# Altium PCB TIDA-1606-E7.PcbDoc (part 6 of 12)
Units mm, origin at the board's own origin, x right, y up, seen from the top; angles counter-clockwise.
Board outline 270 x 345 mm, 4 copper layers (Top Layer, Signal Layer 1, Signal Layer 2, Bottom Layer), stack 2.326 mm thick; 1282 components, 576 nets, 3628 pads, 4132 vias.
Unrouted connection lines stored in the file: 1719.
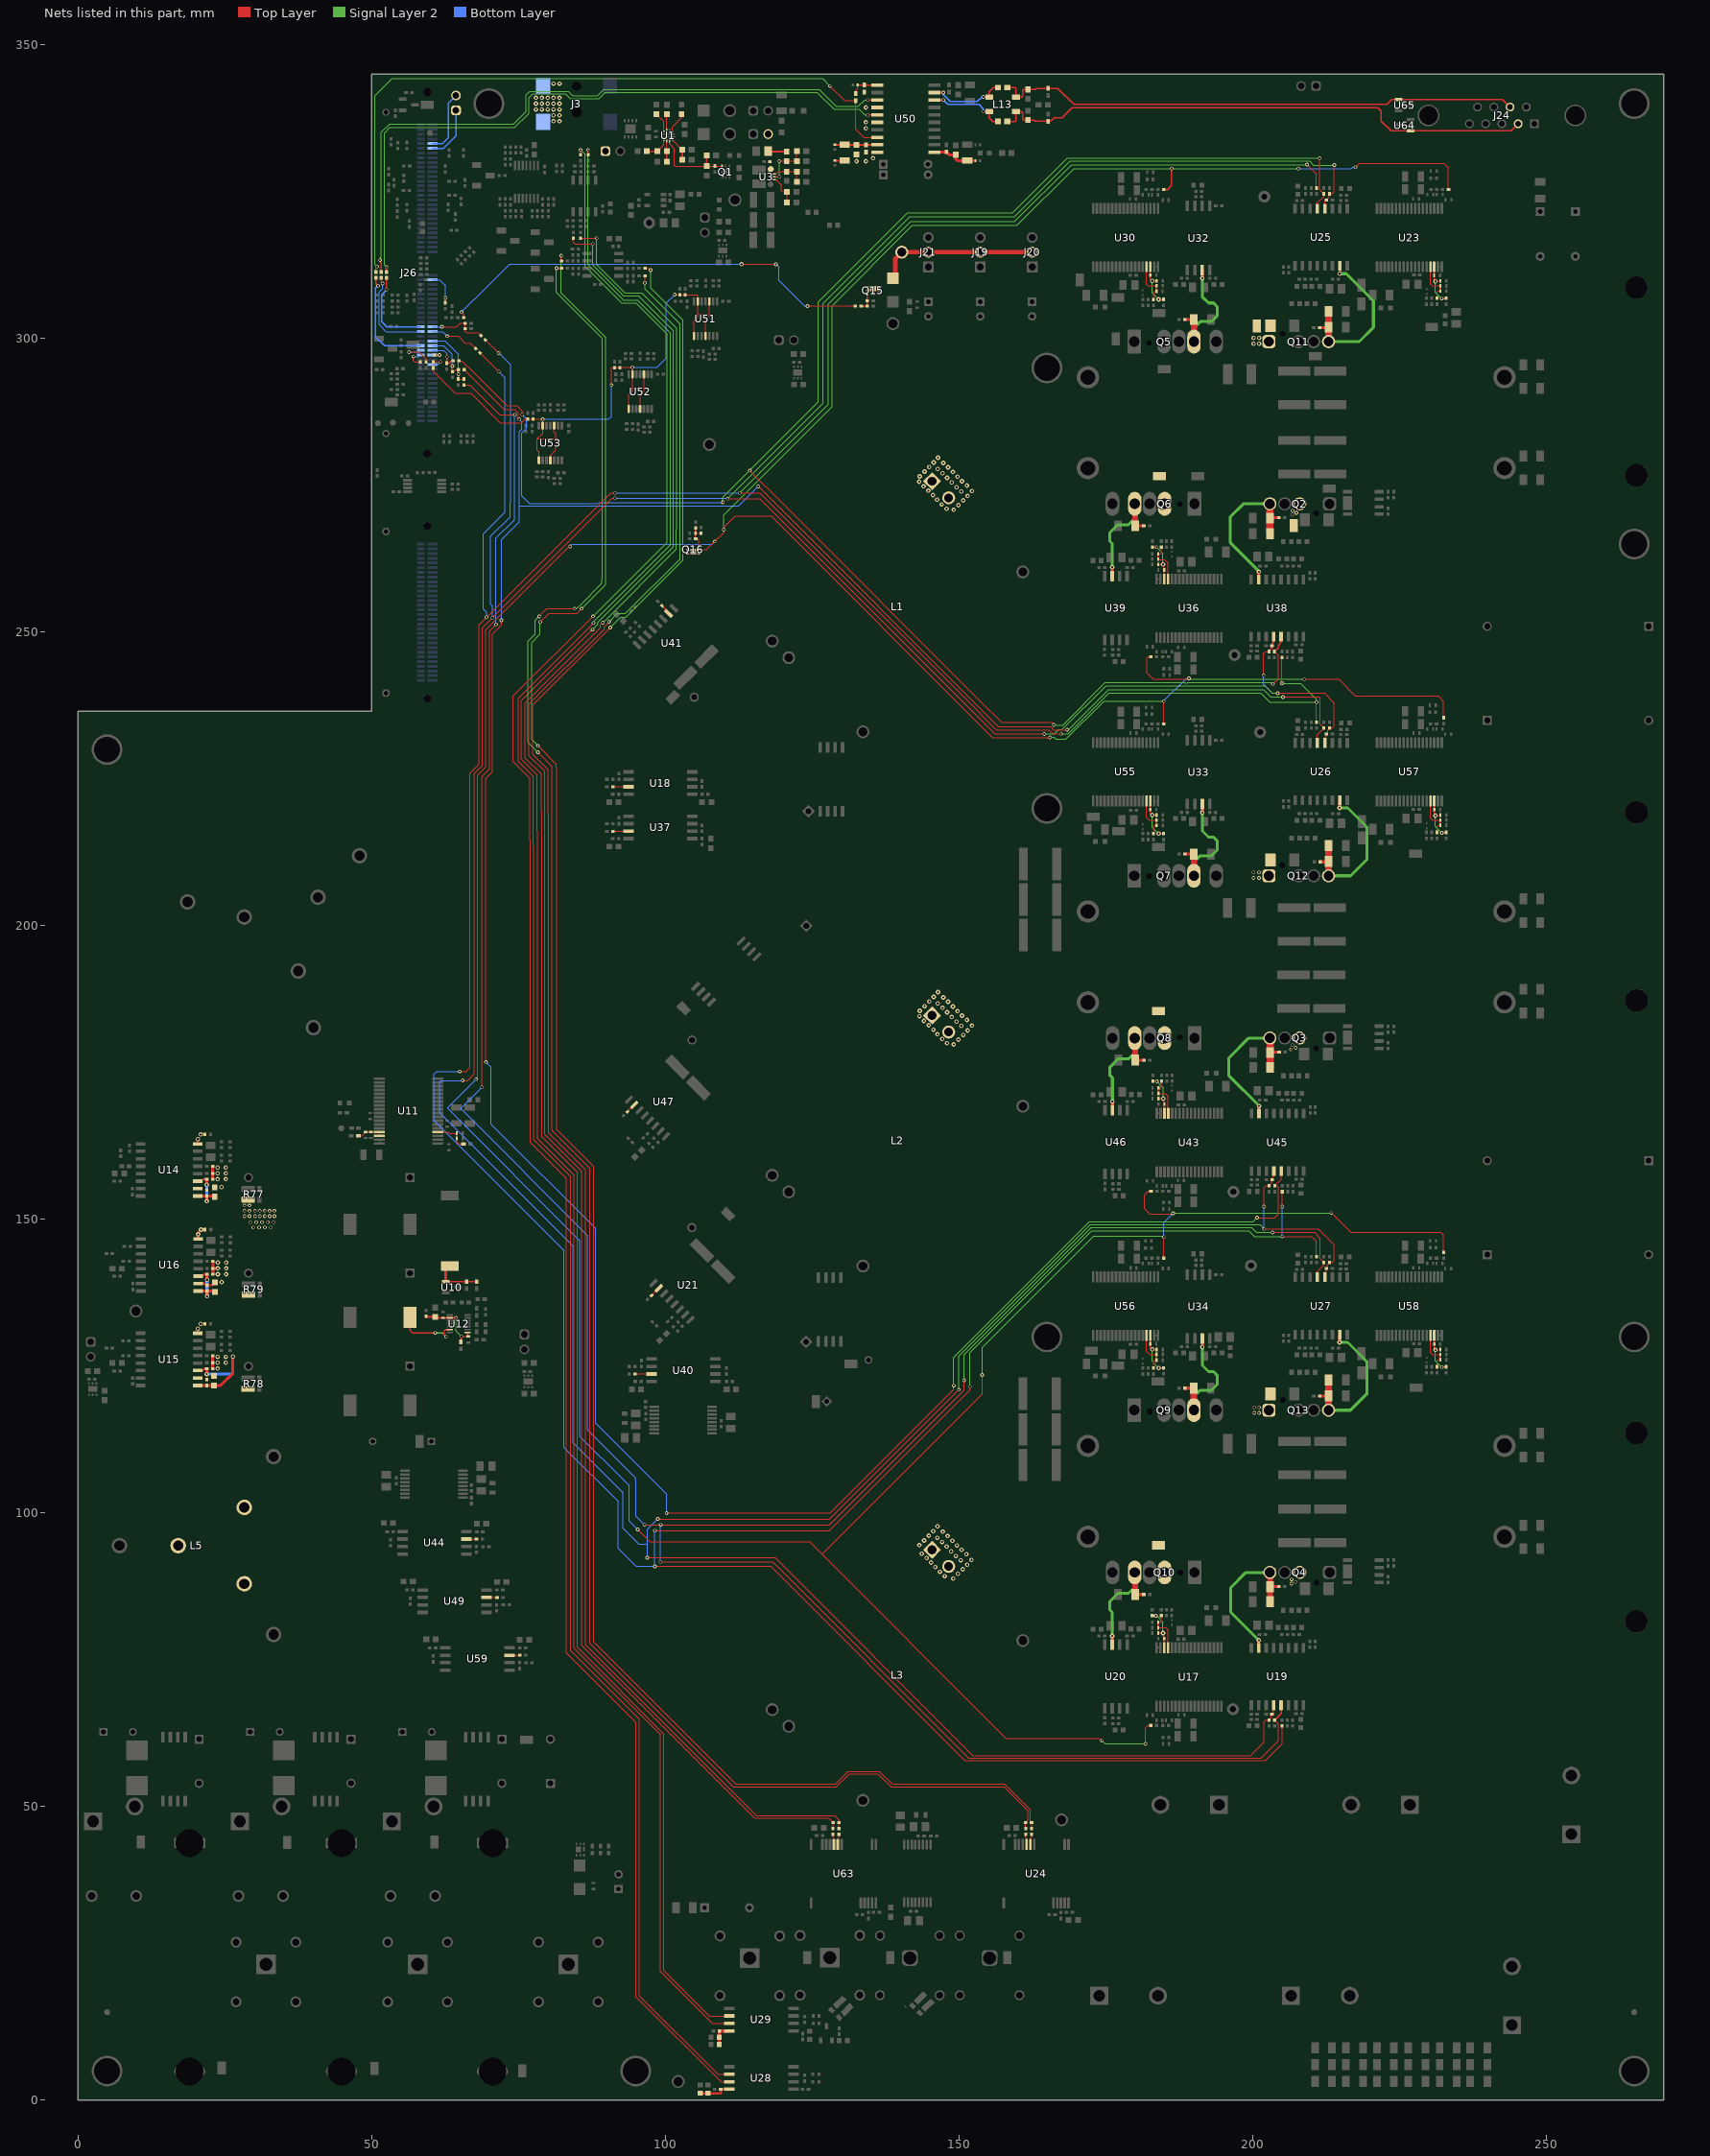
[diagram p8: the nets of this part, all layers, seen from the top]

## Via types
v1: diameter 0.762, hole 0.356, Top Layer to Bottom Layer, tented both sides, 2905 vias
v2: diameter 0.61, hole 0.356, Top Layer to Bottom Layer, tented both sides, 1212 vias
v3: diameter 0.864, hole 0.406, Top Layer to Bottom Layer, tented both sides, 15 vias

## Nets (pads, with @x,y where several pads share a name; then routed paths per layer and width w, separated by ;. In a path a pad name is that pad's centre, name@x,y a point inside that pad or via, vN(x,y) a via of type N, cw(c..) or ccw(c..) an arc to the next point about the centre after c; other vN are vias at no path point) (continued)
AEF_SENS3: C81.1 U12.6 | length 11.1
  Top Layer w0.254: C81.1@56.556,133.295 56.556,131.107 56.981,130.682 v2(60.834,130.682) ; v2(62.712,130) 62.335,130.377 62.335,130.964 62.609,131.238 U12.6@63.365,131.238
  Signal Layer 2 w0.254: v2(60.834,130.682) 62.03,130.682 v2(62.712,130)
AEF_TVS_PT: C7.1 C84.1 R64.2 U10.1 | length 8.2
  Top Layer w0.305: U10.1@62.649,139.401 C7.1@67.902,139.401
  Top Layer w0.508: U10.1@62.649,139.401 62.649,141.348 C84.1@63.347,142.046
AEF_VDD: C92.1 C96.1 C97.1 R71.1 R74.2 U12.2 U12.8 | length 11.2
  Top Layer w0.203: R74.2@65.246,129.167 65.293,129.213 65.293,130.069 v2(65.311,130.088) C96.1@66.389,130.088
  Top Layer w0.254: R71.1@59.333,133.393 C97.1@60.862,133.393 ; C97.1@61.1,133.238 C92.1@62.183,133.238 U12.2@63.365,133.238 v2(64.412,133.238) ; U12.8@66.365,130.738 66.389,130.714 66.389,130.088 66.413,130.064 C96.1@66.5,130.064
  Signal Layer 2 w0.203: v2(64.412,133.238) 64.412,130.987 v2(65.311,130.088)
ALERT_L1: R308.2 U41.4 | length 1.8
  Top Layer w0.229: R308.2@99.466,254.5 100.602,253.364 U41.4@100.602,253.185
ALERT_L2: R340.2 U47.4 | length 1.6
  Top Layer w0.203: R340.2@93.6,168.356 93.6,168.365 U47.4@94.743,169.508
ALERT_L3: R178.2 U21.4 | length 1.7
  Top Layer w0.203: R178.2@97.693,137.054 98.904,138.266 U21.4@98.93,138.266
AMC13x_VDD_LO: C220.1 C221.1 L7.1 U28.8 | length 5.8
  Top Layer w0.381: L7.1@106,1.2 C221.1@107.3,1.2 107.3,1.187 109.537,1.187 109.537,1.806 C220.1@109.456,1.887 U28.8@110.95,1.887
AMC13x_VDD_MID: C269.1 C271.1 L8.2 U29.8 | length 4
  Top Layer w0.5: L8.2@109.237,9.5 C269.1@109.237,10.731 C271.1@109.237,11.8 110.93,11.8 U29.8@110.95,11.82
AMC033_OUT1: R171.1 U44.7 | length 1.7
  Top Layer w0.203: U44.7@66.187,95.56 R171.1@67.89,95.56
AMC033_OUT2: R222.1 U49.7 | length 1.8
  Top Layer w0.203: U49.7@69.613,85.626 R222.1@71.401,85.626
AMC033_OUT3: R251.1 U59.7 | length 1.8
  Top Layer w0.203: U59.7@73.497,75.786 R251.1@75.26,75.786
AMC033_SN_O1: R63.1 U18.7 | length 2.6
  Top Layer w0.203: R63.1@91.1,223.669 U18.7@93.75,223.669
AMC033_SN_O2: R68.1 U37.7 | length 2.7
  Top Layer w0.203: R68.1@91.1,216.104 U37.7@93.75,216.104
AMC033_SN_O3: R73.1 U40.7 | length 2.8
  Top Layer w0.203: R73.1@94.88,123.682 U40.7@97.693,123.682
AMC1302_OUTN_A: R274.1 U29.6 | length 339.8
  Top Layer w0.203: R274.1@85.614,317.089 v2(88.363,317.089) ; v2(89.408,251.603) 89.034,251.228 89.034,250.754 76.2,237.92 76.2,228.52 78.914,225.806 78.914,219.456 78.914,164.185 85.06,158.04 85.06,77.14 99.815,62.385 99.815,22.061 107.516,14.36 U29.6@110.95,14.36
  Signal Layer 2 w0.203: v2(88.363,317.089) 88.363,312.552 93.179,307.737 96.008,307.737 101.929,301.815 101.929,267.462 101.929,264.124 v2(89.408,251.603)
AMC1302_OUTN_B: R241.2 U28.6 | length 362.4
  Top Layer w0.203: R241.2@86.889,331.286 v2(86.889,332.099) v2@86.889,332.118 ; v2(87.82,251.568) 75,238.748 75,227.951 77.552,225.399 77.552,213.627 77.565,213.614 77.565,163.628 83.86,157.333 83.86,76.64 95.562,64.938 95.562,17.852 108.987,4.427 U28.6@110.95,4.427
  Signal Layer 2 w0.203: v2(86.889,332.099) 86.889,312.573 92.884,306.578 95.297,306.578 100.845,301.03 100.845,264.82 87.82,251.795 v2(87.82,251.568)
AMC1302_OUTP_A: R272.1 U29.7 | length 341.5
  Top Layer w0.203: R272.1@84.347,317.089 84.347,316.453 84.697,316.103 v2(87.702,316.103) v2@87.89,316.103 ; v2(87.63,250.444) 75.538,238.352 75.538,228.375 78.251,225.661 78.251,216.154 78.251,163.819 84.45,157.62 84.45,77.031 99.234,62.248 99.234,21.925 108.069,13.09 U29.7@110.95,13.09
  Signal Layer 2 w0.203: v2(87.63,250.444) 88.6,251.414 88.6,251.75 101.397,264.547 101.397,301.306 95.419,307.283 92.915,307.283 87.702,312.496 v2(87.702,316.103)
AMC1302_OUTP_B: R239.2 U28.7 | length 364.1
  Top Layer w0.203: R239.2@85.625,331.286 v2(85.625,332.099) ; v2(87.738,252.692) 74.168,239.122 74.168,227.94 77,225.108 77,214.63 77,163.172 83.148,157.024 83.148,76.252 94.998,64.402 94.998,17.709 109.55,3.157 U28.7@110.95,3.157
  Signal Layer 2 w0.203: v2(85.625,332.099) 86.36,331.363 86.36,312.302 92.592,306.07 95.019,306.07 100.315,300.774 100.315,265.269 v2(87.738,252.692)
AMC_DC_OUT1: C105.2 C106.1 C108.1 U14.1 U14.3 | length 9.2
  Top Layer w0.305: U14.3@21.106,156.52 21.442,156.856 C108.1@21.965,156.856
  Top Layer w0.35: U14.3@20.441,156.52 U14.3@21.106,156.52
  Top Layer w0.5: U14.1@20.441,153.98 C106.1@21.965,153.98 ; v1(21.965,155.909) C108.1@21.965,156.856 ; v1(21.97,153.109) 21.965,153.114 C106.1@21.965,153.98 ; C105.2@23.312,153.856 23.188,153.98 C106.1@21.965,153.98
  Bottom Layer w0.5: v1(21.965,155.909) 21.965,153.114 v1(21.97,153.109)
AMC_DC_OUT2: C114.2 C115.1 C117.1 U15.1 U15.3 | length 19.7
  Top Layer w0.305: U15.3@20.441,124.262 21.261,124.262 21.597,124.598 C117.1@21.965,124.598
  Top Layer w0.5: U15.1@20.441,121.722 C115.1@21.965,121.722 C114.2@23.188,121.722 24.319,121.722 26.409,123.812 v1(26.409,126.671) ; v1(21.965,123.651) C117.1@21.965,124.598
  Bottom Layer w0.5: v1(21.965,123.651) 26.248,123.651 26.409,123.812 v1(26.409,126.671)
AMC_DC_OUT3: C123.2 C124.1 C126.1 U16.1 U16.3 | length 9.2
  Top Layer w0.305: U16.3@20.483,140.335 21.184,140.335 21.52,140.671 C126.1@22.007,140.671
  Top Layer w0.5: U16.1@20.483,137.795 C124.1@22.007,137.795 ; v1(22.007,139.724) C126.1@22.007,140.671 ; v1(22.012,136.924) 22.007,136.929 C124.1@22.007,137.795 ; C123.2@23.354,137.671 23.23,137.795 C124.1@22.007,137.795
  Bottom Layer w0.5: v1(22.007,139.724) 22.007,136.924 v1(22.012,136.924)
AMC_HGND_L1: C105.1 C106.2 C108.2 C109.2 C111.2 FB3.2 U14.2 U14.8 | length 3.7
  Top Layer w0.254: U14.8@20.441,162.87 20.461,162.89 v1(20.461,163.658) ; v1(20.941,164.456) FB3.2@21.62,164.456
  Top Layer w0.5: C108.2@22.965,156.856 C109.2@22.965,157.856 C111.2@22.965,159.06
  other v1: 24.462,155.49 23.812,156.856 25.212,156.856 23.812,157.856 25.212,157.856 23.812,158.856 25.212,158.856
AMC_HGND_L2: C114.1 C115.2 C117.2 C118.2 C120.2 FB6.2 U15.2 U15.8 | length 2.2
  Top Layer w0.5: C117.2@22.965,124.598 C118.2@22.965,125.598 C120.2@22.965,126.802
  other v1: 23.812,124.598 23.812,125.598 25.212,125.598 23.812,126.598 25.212,126.598 20.461,131.4 20.941,132.198
AMC_HGND_L3: C123.1 C124.2 C126.2 C127.2 C129.2 FB9.2 U16.2 U16.8 | length 8.7
  Top Layer w0.35: U16.2@20.483,139.065 21.597,139.065 21.867,138.795 C124.2@22.007,138.795 22.878,138.795 C123.1@23.354,139.271
  Top Layer w0.5: U16.8@20.483,146.685 20.483,147.771 v1(20.983,148.271) FB9.2@21.662,148.271 ; C126.2@23.007,140.671 C127.2@23.007,141.671 ; C129.2@23.007,142.875 C127.2@23.007,141.671 ; v1(23.854,141.671) C127.2@23.007,141.671
  other v1: 24.504,139.305 23.854,140.671 25.254,140.671 25.254,141.671 23.854,142.671 25.254,142.671 20.503,147.473
AUX_IN_PWR: J1.1 J3.1 J3.1A
  other v1: 81.002,336.997 82.002,336.997 81.002,338 82.002,338 78.002,339 79.002,339 80.002,339 81.002,339 82.002,339 78.002,340.003 79.002,340.003 80.002,340.003 81.002,340.003 82.002,340.003 78.002,341 79.002,341 80.002,341 81.002,341 82.002,341 81.002,343.408 82.002,343.408
BUFF_EN: C102.1 C389.1 C470.1 R375.2 R381.2 R413.2 R466.1 U51.1 U51.4 U51.10 U51.13 U52.1 U52.4 U52.10 U52.13 U53.1 U53.4 U53.10 U53.13 | length 116.7
  Top Layer w0.203: R466.1@60.502,295 60.502,294.423 64.226,290.7 66.91,290.7 71.961,285.648 75.525,285.648 76.177,286.3 R413.2@76.602,286.3 C470.1@77.502,286.3 79.126,286.3 v2(79.162,286.265) U53.13@79.162,285.173 79.162,283.835 78.232,282.906 ; U53.1@78.512,279.273 78.512,280.72 78.232,281 78.232,282.906 ; U53.4@80.462,279.273 80.462,280.104 81.393,281.035 81.393,283 ; U53.10@81.112,285.173 81.112,284.089 81.393,283.808 81.393,283 ; v2(90.857,292.07) 90.857,295.039 90.932,295.114 v2(94.431,295.114) 94.452,295.092 U52.13@94.452,293.913 94.452,291.126 93.802,290.476 U52.1@93.802,288.013 ; R381.2@91.406,295.053 R381.2@91.427,295.032 ; 94.452,291.563 96.402,291.563 ; U52.4@95.752,288.013 95.752,290.438 96.402,291.088 U52.10@96.402,293.913 ; v2(101.637,307.471) R375.2@102.546,307.471 C102.1@103.446,307.471 103.46,307.457 105.396,307.457 105.593,307.26 U51.13@105.593,306.331 105.593,304.202 ; U51.1@104.943,300.431 104.943,303.056 105.593,303.706 105.593,304.202 ; U51.4@106.893,300.431 106.893,303.305 107.543,303.955 107.543,304.191 ; U51.10@107.543,306.331 107.543,304.191 ; 78.232,282.906 81.299,282.906 81.393,283 ; 105.593,304.202 105.604,304.191 107.543,304.191
  Bottom Layer w0.203: v2(79.162,286.265) 90.415,286.265 90.857,286.707 v2(90.857,292.07) ; v2(94.431,295.114) 98.65,295.114 100.214,296.678 100.214,306.048 v2(101.637,307.471)
BUFF_EN_IO: J26.26 R466.2 | length 2.9
  Top Layer w0.203: R466.2@60.502,296 v2(61.802,296)
  Bottom Layer w0.203: J26.26@60.402,295.585 61.388,295.585 v2(61.802,296)
CAN_EN: R383.1 R460.2 U50.8 | length 124
  Top Layer w0.203: R460.2@50.762,311.339 50.762,312.045 v2(50.987,312.27) ; v2(128.065,342.997) 130.541,340.521 R383.1@132.438,340.521 132.438,335.635 133.81,334.264 U50.8@136.144,334.264
  Signal Layer 2 w0.203: v2(50.987,312.27) 50.627,312.63 50.627,341.329 53.573,344.275 126.787,344.275 v2(128.065,342.997)
CAN_GND1: C370.2 C371.2 C372.2 C373.2 FB20.2 U50.4 U50.6 U50.10 | length 1.7
  Top Layer w0.305: FB20.2@128.88,330.303 C370.2@130.556,330.303
  other v1: 132.594,330.196 134.2,330.196 135.4,330.708 134.2,335.797 134.2,336.829 134.2,339.344
CAN_GND2: C380.2 C381.2 C382.2 FB19.1 U50.11 | length 8.1
  Top Layer w0.305: C382.2@151.494,330.271 FB19.1@152.841,330.271
  Top Layer w0.508: U50.11@145.844,331.724 147.836,331.724 C380.2@147.907,331.795 148.411,331.29 C381.2@149.474,331.29 149.474,330.54 149.743,330.271 C382.2@151.494,330.271
CAN_RX: R452.2 U50.5 | length 114.5
  Top Layer w0.229: R452.2@52.562,311.339 v2(52.562,312.164)
  Top Layer w0.305: v2(134.499,338.074) U50.5@136.144,338.074
  Signal Layer 2 w0.203: v2(52.562,312.164) 52.215,312.511 52.215,334.991 53.149,335.925 74.365,335.925 76.805,338.365 76.805,341.059 77.438,341.692 83.054,341.692 83.878,340.868 88.746,340.868 89.832,341.954 125.878,341.954 128.742,339.09 133.011,339.09 134.027,338.074 v2(134.499,338.074)
CAN_TX: R458.2 U50.3 | length 115.3
  Top Layer w0.229: v2(51.48,313.375) 51.48,313.032 51.662,312.85 R458.2@51.662,311.339
  Top Layer w0.305: v2(134.499,340.614) U50.3@136.144,340.614
  Signal Layer 2 w0.203: v2(51.48,313.375) 51.48,313.772 51.652,313.944 51.652,335.125 53.095,336.568 74.232,336.568 76.344,338.68 76.344,341.508 76.948,342.111 83.524,342.111 84.26,341.376 88.523,341.376 89.559,342.412 126.245,342.412 129.124,339.533 132.899,339.533 133.979,340.614 v2(134.499,340.614)
CAN_VDD: C370.1 C371.1 C372.1 FB16.2 U50.9 | length 7.3
  Top Layer w0.305: FB16.2@128.88,332.994 U50.9@136.144,332.994
CAN_VIO: C373.1 FB17.2 R383.2 U50.1 | length 4.9
  Top Layer w0.203: R383.2@132.438,341.721 132.438,342.202 132.789,342.552 FB17.2@132.789,343.154
  Top Layer w0.305: FB17.2@132.789,343.154 C373.1@133.949,343.154 U50.1@136.144,343.154
CANEN_IO: J26.33 R460.1 | length 18.7
  Top Layer w0.229: R460.1@50.762,310.339 50.762,309.358 v2(51.118,309.003)
  Bottom Layer w0.229: v2(51.118,309.003) 50.722,308.606 50.722,300.27 52.207,298.785 J26.33@58.402,298.785
CANH: L13.1 R384.2 U50.19 | length 13.2
  Top Layer w0.229: U50.19@145.844,341.884 v2(147.362,341.884) ; v2(154.178,341.138) L13.1@155.205,341.138 155.205,342.013 155.93,342.738 R384.2@156.68,342.738
  Bottom Layer w0.229: v2(147.362,341.884) 147.362,341.567 148.569,340.36 153.138,340.36 153.916,341.138 v2(154.178,341.138)
CANHI: C377.1 J24.7 L13.4 R384.1 R385.2 U65.1 | length 90.3
  Top Layer w0.229: R384.1@158.28,342.738 159.601,342.738 159.755,342.583 L13.4@159.755,341.138 160.735,341.138 160.871,341.274 160.871,342.247 161.036,342.412 R385.2@161.798,342.412 162.996,342.412 163.197,342.613 C377.1@165.218,342.613 166.881,342.613 169.606,339.888 222.906,339.888 223.723,340.705 U65.1@224.872,340.705 242.575,340.705 J24.7@243.873,339.408
CANL: L13.2 R387.2 U50.18 | length 13.2
  Top Layer w0.229: U50.18@145.844,340.614 v2(147.362,340.614) ; v2(154.178,338.638) L13.2@155.205,338.638 155.205,337.604 155.854,336.955 R387.2@156.68,336.955
  Bottom Layer w0.229: v2(147.362,340.614) 148.124,339.852 153.416,339.852 154.178,339.09 v2(154.178,338.638)
CANLO: C379.2 J24.2 L13.3 R386.1 R387.1 U64.1 | length 94
  Top Layer w0.229: R387.1@158.28,336.955 159.601,336.955 159.755,337.11 L13.3@159.755,338.638 160.679,338.638 160.871,338.447 160.871,337.441 161.112,337.2 R386.1@161.798,337.2 162.814,337.2 163.023,336.991 C379.2@165.217,336.991 165.645,336.991 166.27,337.616 167.61,337.616 169.338,339.344 221.353,339.344 221.942,338.754 221.942,337.058 223.635,335.365 U64.1@226.972,335.365 244.055,335.365 J24.2@245.258,336.568
CANRX_IO: J26.41 R452.1 | length 15
  Top Layer w0.229: v2(52.562,308.356) R452.1@52.562,310.339
  Bottom Layer w0.229: v2(52.562,308.356) 52.634,308.356 51.734,307.456 51.734,302.86 52.608,301.985 J26.41@58.402,301.985
CANTX_IO: J26.39 R458.1 | length 15.9
  Top Layer w0.203: R458.1@51.662,310.339 51.662,309.7 51.902,309.46 v2(51.902,309.372)
  Bottom Layer w0.203: v2(51.902,309.372) 51.902,308.546 51.302,307.946 51.302,302.402 52.519,301.185 J26.39@58.402,301.185
CHK_1: L5.AI R77.I2
  other v2: 29.868,148.641 30.868,148.641 31.868,148.641 32.868,148.641 29.366,149.541 30.366,149.541 31.366,149.541 32.366,149.541 33.366,149.541 28.366,150.541 29.236,150.541 30.166,150.541 31,150.541 31.827,150.541 32.653,150.541 33.5,150.541 28.366,151.47 29.236,151.47 30.166,151.47 31,151.47 31.827,151.47 32.653,151.47 33.5,151.47 28.366,152.37 29.236,152.37
CHK_2: L5.AII R78.I2
CHK_3: L5.AIII R79.I2
DACA: J26.112 J27.2 | length 10.8
  Bottom Layer w0.254: J26.112@60.402,333.185 62.066,333.185 63.132,334.252 63.132,340.119 J27.2@64.402,341.389
DACB: J26.110 J27.1 | length 9.2
  Bottom Layer w0.254: J26.110@60.402,332.385 62.266,332.385 64.402,334.522 J27.1@64.402,338.849
DC_RVSEN+: R20.1 U24.11 | length 1.8
  Top Layer w0.203: R20.1@161.4,45.289 161.4,44.83 161.551,44.679 U24.11@161.551,43.55
DC_RVSEN-: R26.1 U24.10 | length 1.8
  Top Layer w0.203: U24.10@162.201,43.55 162.201,44.582 162.4,44.782 R26.1@162.4,45.289
DC_VSEN+: C33.1 R20.2 R22.2 | length 342.2
  Top Layer w0.203: v2(78.352,229.531) 80.75,227.134 80.75,165.142 87.1,158.792 87.1,77.86 111.62,53.34 129.129,53.34 131.373,55.584 136.236,55.584 138.48,53.34 157.685,53.34 161.75,49.275 161.75,47.65 C33.1@161.4,47.3 R20.2@161.4,46.289 ; v2(78.555,252.68) 78.555,252.737 79.818,254 v2(84.582,254) ; v2(81.502,311.962) R22.2@82.37,311.962
  Signal Layer 2 w0.203: v2(78.352,229.531) 76.69,231.194 76.69,248.477 77.91,249.697 77.91,252.035 v2(78.555,252.68) ; v2(81.502,311.962) 81.502,307.833 89.253,300.083 89.253,259.08 89.253,258.324 85.538,254.61 85.534,254.61 85.177,254.253 85.177,254.249 84.928,254 v2(84.582,254)
DC_VSEN-: C33.2 R25.2 R26.2 | length 343.7
  Top Layer w0.203: v2(78.352,230.632) 81.502,227.482 81.502,226.954 81.502,165.419 87.8,159.121 87.8,78.113 112.065,53.848 129,53.848 131.152,56 136.485,56 138.637,53.848 157.752,53.848 162.156,49.444 162.156,47.544 C33.2@162.4,47.3 R26.2@162.4,46.289 ; v2(78.74,251.732) 80.246,253.238 85.025,253.238 v2(85.787,254) ; v2(82.312,314.089) 82.312,313.285 R25.2@82.37,313.226
  Signal Layer 2 w0.203: v2(78.352,230.632) 77.31,231.675 77.31,248.235 78.74,249.665 v2(78.74,251.732) ; v2(82.312,314.089) 82.312,307.813 89.928,300.196 89.928,258.141 v2(85.787,254)
DCDC_EN: C14.1 R11.1 R14.1 U3.6 | length 8.2
  Top Layer w0.203: U3.6@118.569,327.528 v2(119.482,327.528) ; v2(119.482,330.183) 119.502,330.204 R11.1@120.702,330.204 122.413,330.204 122.445,330.237 C14.1@122.445,331.894
  Signal Layer 2 w0.203: v2(119.482,327.528) v2(119.482,330.183)
DCDC_FB: C8.2 R12.1 R13.2 U3.7 | length 5.8
  Top Layer w0.203: U3.7@118.569,328.028 118.927,328.028 119.316,328.417 R13.2@120.702,328.417 R12.1@122.445,328.417 C8.2@122.445,326.679
DCDC_PG: R16.1 R18.2 U3.5 | length 5.4
  Top Layer w0.203: U3.5@118.569,327.028 118.913,327.028 119.785,326.155 119.785,325.202 120.01,324.977 R18.2@120.737,324.977 R16.1@120.737,323.184
DCDC_VIN: C12.1 C13.2 J8.2 R11.2 U3.1 | length 3.2
  Top Layer w0.305: C12.1@117.536,331.894 117.627,331.804 R11.2@120.702,331.804
DCM_RVSEN+: R27.1 U63.11 | length 1.8
  Top Layer w0.203: R27.1@128.598,45.289 128.598,44.675 128.749,44.524 U63.11@128.749,43.55
DCM_RVSEN-: R30.1 U63.10 | length 1.8
  Top Layer w0.203: U63.10@129.399,43.55 129.399,44.526 129.598,44.725 R30.1@129.598,45.289
DCM_VSEN+: C342.1 R27.2 R32.2 | length 307.1
  Top Layer w0.203: v2(90.446,251.753) 89.64,250.947 89.64,250.509 76.86,237.728 76.86,228.965 79.511,226.314 79.511,164.489 85.7,158.3 85.7,77.561 115.191,48.07 127.829,48.07 C342.1@128.598,47.3 R27.2@128.598,46.289 ; v2(96.57,309.501) R32.2@96.57,310.687
  Signal Layer 2 w0.203: v2(90.446,251.753) 91.878,253.185 93.264,253.185 102.522,262.442 102.522,302.497 96.57,308.449 v2(96.57,309.501)
DCM_VSEN-: C342.2 R30.2 R34.2 | length 309.2
  Top Layer w0.203: v2(90.678,250.806) 77.47,237.598 77.47,229.213 80.115,226.568 80.115,219.202 80.115,164.806 86.4,158.521 86.4,77.616 115.516,48.5 128.839,48.5 129.598,47.741 C342.2@129.598,47.3 R30.2@129.598,46.289 ; R34.2@96.57,311.962 97.229,311.962 v2(97.539,311.653)
  Signal Layer 2 w0.203: v2(90.678,250.806) 92.407,252.535 93.316,252.535 102.996,262.215 102.996,303.171 97.539,308.629 v2(97.539,311.653)
DESAT_BOT_L1: D10.1 L1.1 L1.2 Q2.2 Q6.2 Q11.1 TP32.1 TP34.1 TP59.1 | length 0.1
  Top Layer w0.5: Q11.1@202.748,299.543 Q11.1@202.811,299.48
  Top Layer w1: Q2.2@208.057,271.812 Q2.2@208.057,271.85
  other v1: 149.149,270.823 147.929,271.023 149.949,271.629 147.106,271.761 150.749,272.429 146.3,272.561 151.511,273.2 145.6,273.333 150.436,273.951 152.249,274.023 144.829,274.096 149.613,274.689 144.006,274.833 151.385,274.979 148.808,275.489 143.263,275.623 150.562,275.717 148.008,276.289 149.791,276.479 143.372,276.523 147.236,277.051 148.991,277.279 144.172,277.329 146.413,277.789 148.185,278.079 144.972,278.129 147.362,278.817 145.734,278.9 146.472,279.723 200.2,299.12 201.141,299.12 200.2,300.1 201.141,300.1
  other v2: 206.805,270.04 207.496,270.3 206.833,270.695
DESAT_BOT_L2: D11.1 L2.1 L2.2 Q3.2 Q8.2 Q12.1 TP61.1 | length 0.1
  Top Layer w0.5: Q12.1@202.813,208.511 Q12.1@202.903,208.602
  other v1: 149.149,179.804 148,180 149.949,180.609 147.177,180.738 150.749,181.409 146.371,181.538 151.511,182.181 145.671,182.31 150.436,182.932 152.249,183.004 144.9,183.072 149.613,183.67 144.077,183.81 151.385,183.96 148.808,184.47 143.334,184.6 150.562,184.698 148.008,185.27 149.791,185.46 143.372,185.504 147.236,186.032 148.991,186.26 144.172,186.309 146.413,186.77 148.185,187.06 144.972,187.109 147.362,187.798 145.734,187.881 146.472,188.704
  other v2: 206.575,178.947 207.364,179.234 206.805,179.681 200.178,208.156 201.13,208.15 200.178,209.097 201.13,209.091
DESAT_BOT_L3: D12.1 L3.1 L3.2 Q4.2 Q10.2 Q13.1 TP62.1 | length 0
  Top Layer w0.203: D12.1@202.813,120.167 D12.1@202.84,120.193
  other v1: 149.066,88.83 147.623,89.262 149.866,89.635 146.8,90 150.666,90.435 145.994,90.8 151.429,91.207 145.294,91.572 150.354,91.958 152.166,92.03 144.523,92.335 149.531,92.695 151.302,92.986 143.7,93.072 148.725,93.495 150.479,93.723 147.925,94.295 149.708,94.486 143.289,94.53 147.154,95.058 148.908,95.286 144.089,95.335 146.331,95.795 148.102,96.086 144.889,96.135 147.279,96.823 145.652,96.907 146.389,97.73
  other v2: 206.627,87.975 207.366,88.265 206.665,88.684 200.343,117.066 201.146,117.066 200.343,118.007 201.146,118.007
EF_dVdt: C5.1 U1.7 | length 3.6
  Top Layer w0.203: U1.7@101.265,335.3 101.242,335.323 101.242,336.047 102.808,337.613 C5.1@102.808,338.212
EF_EN: R1.1 R5.2 U1.1 | length 4.2
  Top Layer w0.203: R5.2@98.69,331.9 99.815,333.025 U1.1@99.815,333.8
  Top Layer w0.254: R1.1@96.902,331.9 R5.2@98.69,331.9
EF_ILIM: R3.2 U1.9 | length 2.7
  Top Layer w0.203: U1.9@100.29,335.45 R3.2@100.29,338.2
EF_ITIMER: C4.1 U1.10 | length 3.5
  Top Layer w0.203: C4.1@98.51,338.212 99.802,336.92 99.802,335.313 U1.10@99.815,335.3
EF_OVLO: R5.1 R8.2 U1.2 | length 3.6
  Top Layer w0.203: R8.2@100.29,330.116 R8.2@100.306,330.1 ; R5.1@100.29,331.9 U1.2@100.29,333.65
  Top Layer w0.254: R8.2@100.29,330.116 R5.1@100.29,331.9
EF_PG: C6.1 Q1.3 R6.1 R9.2 U1.3 | length 14.4
  Top Layer w0.203: U1.3@100.74,333.65 100.74,333.175 101.602,332.313 101.602,329.541 101.774,329.37 R9.2@107.076,329.37 C6.1@108.479,329.37 Q1.3@109.679,329.37 ; R6.1@107.076,331.161 R6.1@107.085,331.17
  Top Layer w0.254: R9.2@107.076,329.37 R6.1@107.076,331.161
EF_PGTH: R2.1 R4.2 U1.4 | length 4
  Top Layer w0.203: U1.4@101.265,333.8 102.919,332.147 R2.1@102.925,332.147
  Top Layer w0.254: R4.2@102.925,330.448 R2.1@102.925,332.147
EN_DC_IO: J26.31 R464.1 | length 6
  Top Layer w0.203: v2(56.388,297.688) 58.119,297.688 59.302,296.505 R464.1@59.302,296
  Bottom Layer w0.203: v2(56.388,297.688) 56.44,297.74 58.156,297.74 J26.31@58.402,297.985
EN_DCDC_GATES_BUF: Q16.1 Q16.2 Q16.5 Q16.6 Q16.8 R351.1 R353.1 R361.1 R363.1 R364.1 R446.1 R447.1 R448.1 R450.1 | length 816.1
  Top Layer w0.203: v2(67.818,173.854) 68.106,174.142 68.106,174.498 68.106,225.661 69.5,227.055 69.5,250.448 83.655,264.603 v2(83.859,264.603) ; v2(95.311,97.216) 97.427,95.1 124.6,95.1 158.034,61.666 173.954,61.666 v2(174.385,61.235) ; Q16.6@103.825,263.393 Q16.1@105.775,263.393 ; Q16.5@103.825,264.043 Q16.2@105.775,264.043 107.063,264.043 v2(108.456,265.435) 109.982,266.961 v2(109.982,267.462) 109.982,267.803 111.941,269.762 118.047,269.762 155.32,232.489 155.758,232.051 165.493,232.051 v2(165.532,232.09) ; 126.714,92.986 154,120.273 v2(154,123.5) ; v2(181.797,60.703) 181.797,63.429 181.8,63.432 181.797,63.435 182.198,63.836 R364.1@182.703,63.836 ; R448.1@182.701,245.798 182.2,245.798 182.031,245.628 182.031,243.064 183.094,242 189.018,242 189.174,242.155 v2(189.201,242.128) ; R450.1@182.742,154.832 182.3,154.832 181.597,154.129 181.597,151.845 182.54,150.901 186.351,150.901 v2(186.5,151.051) ; R363.1@184.924,143.405 v2(184.924,147) ; R361.1@184.924,234.4 v2(184.924,238.252) ; v2(208.854,242) 214.684,242 217.532,239.152 231.603,239.152 232.548,238.208 R351.1@232.548,235.428 ; v2(213.412,151.1) 213.512,151.1 216.784,147.828 232.011,147.828 232.548,147.292 R353.1@232.548,144.396 ; v2(217.546,329.185) 218.231,329.87 232.584,329.87 233.381,329.073 R446.1@233.381,325.405
  Top Layer w0.229: R447.1@184.922,325.368 185.534,325.368 186.252,326.086 v2(186.252,328.93)
  Signal Layer 2 w0.203: v2(109.982,267.462) 109.982,269.933 128.479,288.431 128.479,305.602 142.13,319.253 159.92,319.253 169.598,328.93 v2(186.252,328.93) v2(207.815,328.93) ; v2(154,123.5) 154,128.179 173.014,147.193 184.731,147.193 v2(184.924,147) ; v2(165.532,232.09) 166.211,232.09 166.542,231.759 168.279,231.759 174.772,238.252 v2(184.924,238.252) ; v2(174.385,61.235) 174.92,60.7 181.794,60.7 v2(181.797,60.703) ; v2(186.5,151.051) 213.363,151.051 v2(213.412,151.1) ; v2(189.201,242.128) 188.97,242.128 188.878,242.037 208.818,242.037 v2(208.854,242)
  Bottom Layer w0.203: v2(67.818,173.854) 62.98,169.016 62.98,168.92 85.522,146.378 85.522,113.023 92.835,105.71 92.853,105.71 93.873,104.689 93.873,98.654 v2(95.311,97.216) ; v2@83.789,264.674 v2(83.859,264.603) 84.181,264.925 107.946,264.925 v2(108.456,265.435) ; v2(184.924,147) 184.924,149.475 v2(186.5,151.051) ; v2(184.924,238.252) 184.924,238.344 188.708,242.128 v2(189.201,242.128) ; v2(207.815,328.93) 207.83,328.915 216.827,328.915 217.097,329.185 v2(217.546,329.185)
EN_FET_GATE: C394.1 Q16.3 R433.1 R434.1 R455.2 | length 4.6
  Top Layer w0.203: Q16.3@105.775,264.693 105.775,265.888 C394.1@105.205,265.888 105.183,265.91 R434.1@105.183,266.835 R433.1@106.123,266.835
  Top Layer w0.305: R434.1@105.183,266.835 105.192,266.844 R455.2@105.192,267.728
EN_RY_IO: J26.29 R465.1 | length 3.3
  Top Layer w0.203: v2(57.15,296.926) 57.15,296.29 57.44,296 R465.1@58.317,296
  Bottom Layer w0.203: v2(57.15,296.926) 57.164,296.94 58.156,296.94 J26.29@58.402,297.185
ENA_AEF: C95.1 R109.1 R111.2 U11.4 | length 6
  Top Layer w0.203: U11.4@61.293,164.871 63.051,164.871 63.254,164.668 C95.1@64.516,164.668 R111.2@64.516,163.802 64.516,163.286 64.945,162.857 R109.1@65.654,162.857
FAN_CTRL: R130.1 R445.1 | length 75.8
  Top Layer w0.203: v2(65.341,304.488) 65.702,304.127 R445.1@65.702,303.6 ; v1(113,312.649) v2(118.872,312.649) ; v2(124.231,305.537) 132.363,305.537 R130.1@132.4,305.5
  Bottom Layer w0.203: v2(65.341,304.488) 67.543,306.69 67.564,306.69 73.574,312.7 73.643,312.631 73.661,312.649 v1(113,312.649) ; v2(118.872,312.649) 119.349,312.172 119.349,309.937 123.749,305.537 v2(124.231,305.537)
FAN_CTRL_BU: J26.62 R437.2 | length 5.5
  Top Layer w0.203: R437.2@62.602,306.101 v2(62.602,306.9)
  Bottom Layer w0.203: J26.62@60.402,309.985 61.637,309.985 62.602,309.02 v2(62.602,306.9)
FAN_GATE: C417.1 Q15.3 R130.2 R131.2 | length 3.1
  Top Layer w0.254: R130.2@133.4,305.5 R131.2@134.425,305.5 C417.1@134.425,306.4 Q15.3@134.425,307.525
FAN_SN: D6.2 J19.2 J20.2 J21.2 Q15.1 Q15.2 Q15.5 Q15.6 Q15.8 TP64.1 | length 31
  Top Layer w0.254: Q15.2@134.425,308.175 Q15.5@136.375,308.175 ; Q15.1@134.425,308.825 Q15.6@136.375,308.825
  Top Layer w0.762: D6.2@139.2,310.281 139.2,313.6 TP64.1@140.3,314.7 J21.2@144.829,314.7 J19.2@153.662,314.7 J20.2@162.495,314.7
FB_AEF: C93.1 R39.1 R40.2 U11.33 U11.34 | length 4.5
  Top Layer w0.203: R39.1@47.774,164.221 48.361,164.221 R40.2@49.011,164.871 ; R40.2@49.011,164.871 U11.33@51.343,164.871 U11.34@51.343,164.221
FBVDD_MID1: C244.1 R256.2 R510.1 U30.34 | length 7.7
  Top Layer w0.203: U30.34@182.628,312.215 C244.1@182.628,310.776 182.628,310.131 v1(182.941,309.818) R256.2@183.699,309.818 ; v1(184.043,306.663) R510.1@184.868,306.663
  Signal Layer 2 w0.203: v1(182.941,309.818) 182.941,307.765 v1(184.043,306.663)
FBVDD_MID2: C403.1 R505.2 R530.1 U55.34 | length 7.7
  Top Layer w0.203: U55.34@182.63,221.247 C403.1@182.63,219.807 182.63,219.163 v1(182.943,218.85) R505.2@183.701,218.85 ; v1(184.045,215.694) R530.1@184.87,215.694
  Signal Layer 2 w0.203: v1(182.943,218.85) 182.943,216.797 v1(184.045,215.694)
FBVDD_MID3: C411.1 R513.2 R538.1 U56.34 | length 7.7
  Top Layer w0.203: U56.34@182.63,130.251 C411.1@182.63,128.812 182.63,128.167 v1(182.943,127.855) R513.2@183.701,127.855 ; v1(184.045,124.699) R538.1@184.87,124.699
  Signal Layer 2 w0.203: v1(182.943,127.855) 182.943,125.802 v1(184.045,124.699)
FBVDD_SN_L1: C288.1 R173.1 R285.2 U36.34 | length 7.5
  Top Layer w0.203: R173.1@182.99,264.498 183.667,264.498 v2(183.698,264.467) ; R285.2@183.958,261.535 v1(184.775,261.535) 184.775,261.321 184.974,261.121 C288.1@184.974,260.598 U36.34@184.974,259.035
  Signal Layer 2 w0.203: v2(183.698,264.467) 184.775,263.39 v1(184.775,261.535)
FBVDD_SN_L2: C331.1 R319.1 R324.2 U43.34 | length 7.5
  Top Layer w0.203: R319.1@183.031,173.532 183.709,173.532 v2(183.739,173.501) ; R324.2@184,170.569 v1(184.816,170.569) 185.016,170.37 C331.1@185.016,169.632 U43.34@185.016,168.069
  Signal Layer 2 w0.203: v2(183.739,173.501) 184.816,172.424 v1(184.816,170.569)
FBVDD_SN_L3: C144.1 R150.1 R155.2 U17.34 | length 7.5
  Top Layer w0.203: R150.1@182.945,82.534 182.975,82.503 v2(183.566,82.503) ; R155.2@183.96,79.572 v1(184.777,79.572) 184.976,79.372 C144.1@184.976,78.634 U17.34@184.976,77.074
  Signal Layer 2 w0.203: v2(183.566,82.503) 183.7,82.503 184.777,81.426 v1(184.777,79.572)
FBVDD_VDC-1: C184.1 R190.1 R194.2 U23.34 | length 7.6
  Top Layer w0.203: U23.34@230.957,312.215 230.957,310.8 230.957,309.943 v1(231.16,309.741) 231.222,309.803 R194.2@231.996,309.803 ; v2(232.232,306.809) 232.945,306.809 R190.1@233.002,306.866
  Signal Layer 2 w0.203: v1(231.16,309.741) 231.16,307.881 v2(232.232,306.809)
FBVDD_VDC-2: C419.1 R252.1 R533.2 U57.34 | length 7.4
  Top Layer w0.203: U57.34@230.959,221.247 C419.1@230.959,219.781 230.959,219.168 231.219,218.908 231.219,218.829 231.224,218.834 R533.2@231.998,218.834 ; v2@232.291,215.898 R252.1@233.004,215.898
  Signal Layer 2 w0.203: v1(231.162,218.772) 231.162,216.913 v2(232.234,215.841)
FBVDD_VDC-3: C427.1 R281.1 R541.2 U58.34 | length 7.6
  Top Layer w0.203: U58.34@230.959,130.251 C427.1@230.959,128.786 230.959,127.98 v1(231.162,127.777) 231.936,127.777 R541.2@231.998,127.839 ; v2(232.234,124.845) 232.291,124.902 R281.1@233.004,124.902
  Signal Layer 2 w0.203: v1@231.16,127.772 231.16,125.913 v2@232.232,124.841
FBVEE_MID1: C245.1 R257.2 R511.1 U30.33 | length 7.7
  Top Layer w0.203: U30.33@181.978,312.215 181.978,309.202 182.204,308.976 C245.1@183.699,308.976 183.699,308.009 183.156,308.009 R511.1@183.156,306.646
FBVEE_MID2: C404.1 R506.2 R531.1 U55.33 | length 7.4
  Top Layer w0.203: U55.33@181.98,221.247 181.98,218.517 182.489,218.008 C404.1@183.701,218.008 ; R531.1@183.158,215.678 183.158,216.941 183.321,217.104 R506.2@183.701,217.104 C404.1@183.701,217.942
FBVEE_MID3: C412.1 R514.2 R539.1 U56.33 | length 7.5
  Top Layer w0.203: U56.33@181.98,130.251 181.98,127.589 182.556,127.013 C412.1@183.701,127.013 R514.2@183.701,126.04 183.701,125.992 183.158,125.992 R539.1@183.158,124.682
FBVEE_SN_L1: C289.1 R259.1 R286.2 U36.33 | length 7.1
  Top Layer w0.203: C289.1@183.959,262.425 184.011,262.373 185.017,262.373 185.644,261.746 U36.33@185.644,259.056 ; C289.1@183.959,262.52 R286.2@183.959,263.334 184.336,263.334 184.492,263.489 R259.1@184.492,264.498
  Top Layer w0.35: U36.33@185.624,259.035 U36.33@185.644,259.056
FBVEE_SN_L2: C332.1 R320.1 R325.2 U43.33 | length 7.4
  Top Layer w0.203: C332.1@184,171.459 185.165,171.459 185.666,170.959 U43.33@185.666,168.069 ; R325.2@184,172.273 184.376,172.273 184.533,172.431 R320.1@184.533,173.532 ; C332.1@184.002,171.459 R325.2@184.002,172.405
FBVEE_SN_L3: C145.1 R151.1 R156.2 U17.33 | length 7.4
  Top Layer w0.203: R151.1@184.494,82.534 184.494,81.528 184.366,81.4 R156.2@183.961,81.4 C145.1@183.961,80.462 185.255,80.462 185.626,80.091 U17.33@185.626,77.074
FBVEE_VDC-1: C185.1 R191.1 R195.2 U23.33 | length 7.3
  Top Layer w0.203: U23.33@230.307,312.215 230.307,309.24 230.589,308.958 C185.1@231.996,308.958 R195.2@231.996,308.095 231.647,308.095 231.455,307.903 R191.1@231.455,306.866
FBVEE_VDC-2: C420.1 R253.1 R534.2 U57.33 | length 7.3
  Top Layer w0.203: U57.33@230.309,221.247 230.309,218.34 230.659,217.989 R534.2@231.998,217.989 C420.1@231.998,217.127 231.653,217.127 231.457,216.931 R253.1@231.457,215.898
FBVEE_VDC-3: C428.1 R302.1 R542.2 U58.33 | length 7.3
  Top Layer w0.203: U58.33@230.309,130.251 230.309,127.321 230.636,126.994 C428.1@231.998,126.994 R542.2@231.998,126.132 231.657,126.132 231.457,125.932 R302.1@231.457,124.902
FLT_BU: J26.30 R435.2 | length 2.1
  Top Layer w0.229: R435.2@60.702,297.185 v2(61.602,297.185)
  Bottom Layer w0.229: J26.30@60.402,297.185 v2(61.602,297.185)
G_FLT1_IO: C388.1 J26.32 R463.2 | length 5.5
  Top Layer w0.229: v2(62.84,296.9) C388.1@62.84,295.8 63.153,295.8 63.553,296.2 R463.2@63.901,296.2
  Bottom Layer w0.203: J26.32@60.402,297.985 62.322,297.985 62.84,297.468 v2(62.84,296.9)
G_FLT2_IO: C387.1 J26.34 R462.2 | length 8.1
  Top Layer w0.203: v2@63.778,295.377 v2(63.778,295.3) C387.1@63.778,294.4 64.068,294.4 64.368,294.7 R462.2@64.802,294.7
  Bottom Layer w0.203: J26.34@60.402,298.785 62.301,298.785 63.778,297.308 v2(63.778,295.3)
G_FLT3_IO: C386.1 J26.36 R459.2 | length 10.5
  Top Layer w0.203: v2(64.802,293.913) C386.1@64.802,293.1 R459.2@65.753,293.1
  Bottom Layer w0.203: J26.36@60.402,299.585 62.517,299.585 64.802,297.3 v2(64.802,293.913)
G_RDY_IO: C481.2 J26.42 R299.1 R359.2 | length 10.2
  Top Layer w0.203: v2(62.002,302) 64.502,302 65.102,302.6 C481.2@65.974,302.6 R299.1@65.974,301.7 65.974,301.207 66.18,301 68.152,301 R359.2@68.652,300.5
  Bottom Layer w0.203: J26.42@60.402,301.985 61.988,301.985 v2(62.002,302)
G_RST_IO: J26.40 R457.2 | length 8.6
  Top Layer w0.203: v2(62.902,300.4) 64.796,300.4 65.996,299.2 66.85,299.2 R457.2@67.761,298.289
  Bottom Layer w0.203: J26.40@60.402,301.185 62.102,301.185 62.888,300.4 v2(62.902,300.4)
GATE_BOT_L1: Q11.4 R82.2 R203.2 R204.2 U25.7 | length 28.8
  Top Layer w0.4: U25.7@214.88,312.358 214.88,311.034 v1(214.882,311.032)
  Top Layer w0.5: R82.2@211.438,301.856 R203.2@212.971,301.856
  Top Layer w1.2: Q11.4@212.971,299.48 212.971,301.856 R204.2@212.971,304.6
  Signal Layer 2 w0.5: Q11.4@212.971,299.48 218.184,299.48 220.6,301.896 220.6,306.424 215.988,311.037 214.887,311.037 v1(214.882,311.032)
GATE_BOT_L2: Q12.4 R83.2 R218.2 R219.2 U26.7 | length 26.8
  Top Layer w0.5: R83.2@211.64,210.888 R218.2@212.973,210.888 ; v1(214.853,220.068) 214.882,220.098 U26.7@214.882,221.39
  Top Layer w1.2: Q12.4@212.973,208.511 212.973,210.888 R219.2@212.973,213.428
  Signal Layer 2 w0.5: Q12.4@212.973,208.511 216.71,208.511 219.487,211.288 219.487,216.813 216.232,220.068 v1(214.853,220.068)
GATE_BOT_L3: Q13.4 R84.2 R233.2 R235.2 U27.7 | length 27.2
  Top Layer w0.5: R84.2@211.438,119.9 R233.2@212.973,119.9 ; v1(214.853,129.073) 214.882,129.103 U27.7@214.882,130.394 U27.7@214.853,130.365
  Top Layer w1.2: Q13.4@212.973,117.516 R235.2@212.973,122.605
  Signal Layer 2 w0.5: Q13.4@212.971,117.511 216.708,117.511 219.485,120.288 219.485,125.813 216.23,129.068 v1@214.851,129.068
GATE_MID_L1: Q5.4 R85.2 R258.2 U32.7 | length 21.8
  Top Layer w0.5: R85.2@188.503,303.23 R258.2@190.043,303.23 ; v1(191.464,310.251) 191.465,310.252 U32.7@191.465,311.668
  Top Layer w1: Q5.4@190.043,299.48 R258.2@190.043,303.23
  Signal Layer 2 w0.5: Q5.4@190.043,299.48 190.043,301.813 191.12,302.891 193.04,302.891 193.993,303.843 193.993,305.438 193.378,306.053 192.534,306.053 191.464,307.123 v1(191.464,310.251)
GATE_MID_L2: Q7.4 R86.2 R262.2 U33.7 | length 21.7
  Top Layer w0.5: R86.2@188.505,212.262 R262.2@189.99,212.262 ; v1(191.466,219.282) v1(191.466,219.282) U33.7@191.467,220.7
  Top Layer w1: Q7.4@190.045,208.511 R262.2@190.045,212.207
  Signal Layer 2 w0.5: Q7.4@190.045,208.511 190.045,210.845 191.122,211.922 193.042,211.922 193.995,212.875 193.995,214.47 193.38,215.085 192.536,215.085 191.466,216.155 v1(191.466,219.282)
GATE_MID_L3: Q9.4 R87.2 R266.2 U34.7 | length 21.8
  Top Layer w0.5: R87.2@188.505,121.266 R266.2@190.007,121.266 ; v1(191.466,128.287) 191.467,128.288 U34.7@191.467,129.705
  Top Layer w1.2: R266.2@190.007,121.266 190.007,117.554 Q9.4@190.045,117.516
  Signal Layer 2 w0.5: Q9.4@190.045,117.516 190.045,119.85 191.122,120.927 193.042,120.927 193.995,121.88 193.995,123.474 193.38,124.089 192.536,124.089 191.466,125.159 v1(191.466,128.287)
GATE_MID_SN_L1: Q6.4 R93.2 R303.2 U39.7 | length 20.5
  Top Layer w0.5: U39.7@176.119,259.568 v1(176.119,261.029) ; R303.2@180.028,268.1 R93.2@181.513,268.1
  Top Layer w1: Q6.4@179.973,271.85 180.028,271.795 R303.2@180.028,268.1
  Signal Layer 2 w0.5: v1(176.119,261.029) 176.119,265.081 175.7,265.5 175.7,266.9 177.1,268.3 178.9,268.3 179.973,269.373 Q6.4@179.973,271.85
GATE_MID_SN_L2: Q8.4 R341.2 R350.2 U46.7 | length 20.5
  Top Layer w0.5: v1(176.161,170.063) 176.169,170.055 U46.7@176.169,168.61 ; R341.2@180.07,177.134 R350.2@181.555,177.134
  Top Layer w1: Q8.4@179.975,180.882 180.07,180.787 R341.2@180.07,177.134
  Signal Layer 2 w0.5: v1(176.161,170.063) 176.161,174.115 175.742,174.534 175.742,175.934 177.142,177.334 178.942,177.334 180.015,178.407 Q8.4@180.015,180.884
GATE_MID_SN_L3: Q10.4 R81.2 R172.2 U20.7 | length 20.5
  Top Layer w0.5: U20.7@176.121,77.604 v1(176.121,79.065) ; R172.2@180.03,86.136 R81.2@181.515,86.136
  Top Layer w1: Q10.4@179.975,89.887 180.03,89.832 R172.2@180.03,86.136
  Signal Layer 2 w0.5: v1(176.121,79.065) 176.121,83.117 175.702,83.536 175.702,84.936 177.102,86.336 178.902,86.336 179.975,87.409 Q10.4@179.975,89.887
GATE_TOP_L1: Q2.4 R88.2 R294.2 R295.2 U38.7 | length 26.9
  Top Layer w0.5: U38.7@201.097,259.002 U38.7@201.068,258.972 201.068,260.264 v1(201.097,260.293) ; R294.2@202.977,269.474 R88.2@204.51,269.474
  Top Layer w1.2: R295.2@202.977,266.934 202.977,269.474 Q2.4@202.977,271.85
  Signal Layer 2 w0.5: 196.248,265.232 201.097,260.382 v1(201.097,260.293) v1@201.097,260.197 ; 196.25,265.232 196.25,269.65 198.45,271.85 Q2.4@202.977,271.85
GATE_TOP_L2: Q3.4 R99.2 R333.2 R334.2 U45.7 | length 26.5
  Top Layer w0.5: U45.7@201.109,168.006 201.109,169.298 v1(201.139,169.327) ; R333.2@203.019,178.508 R99.2@204.552,178.508
  Top Layer w1: Q3.4@202.979,180.882 Q3.4@203.019,180.842
  Top Layer w1.2: R334.2@203.019,175.968 203.019,178.508 Q3.4@203.019,180.842
  Signal Layer 2 w0.5: v1(201.139,169.327) 196,174.466 196,177.5 199.382,180.882 Q3.4@202.979,180.882
GATE_TOP_L3: Q4.4 R80.2 R164.2 R165.2 U19.7 | length 26.5
  Top Layer w0.5: U19.7@201.07,77.011 201.07,78.3 v1(201.099,78.329) ; R164.2@202.979,87.51 R80.2@204.512,87.51
  Top Layer w1: R165.2@202.979,84.97 202.979,87.51 Q4.4@202.979,89.887
  Signal Layer 2 w0.5: v1(201.099,78.329) 196.298,83.131 196.298,87.298 198.887,89.887 Q4.4@202.979,89.887
GATES_FLT_L1: R199.1 R290.1 R463.1 U25.13 U38.13 | length 329.2
  Top Layer w0.203: R463.1@64.901,296.2 65.402,296.2 67.404,294.198 73.038,288.565 74.76,288.565 75.692,287.632 v2(75.692,287.02) ; v2(114.425,277.528) 114.425,277.5 119.623,272.302 153.812,238.114 157.3,234.625 165.775,234.625 v2(166.2,234.2) ; v2(203.5,241.2) 204.415,242.115 204.415,246.052 R290.1@203.77,246.698 ; U25.13@211.07,322.108 211.07,323.124 212.178,324.232 R199.1@212.178,324.632 211.461,325.35 v2(211.461,330.708)
  Top Layer w0.229: R290.1@203.77,246.698 203.77,246.717 204.398,247.345 204.398,247.732 204.878,248.212 U38.13@204.878,249.222
  Signal Layer 2 w0.203: v2(109.846,272.1) 109.846,273 v2@114.4,277.554 ; v2(114.425,277.528) 126.1,289.203 126.1,306.186 141.314,321.4 159.143,321.4 168.451,330.708 v2(211.461,330.708) ; v2(166.2,234.2) 167.768,234.2 174.968,241.4 188.485,241.4 188.495,241.39 189,241.39 189.01,241.4 203.3,241.4 v2(203.5,241.2)
  Bottom Layer w0.203: v2(75.692,287.02) 76.404,286.308 76.404,284.702 75.59,283.889 75.59,273.21 76.918,271.882 88.501,271.882 88.719,272.1 v2(109.846,272.1)
GATES_FLT_L2: R214.1 R329.1 R462.1 U26.13 U45.13 | length 518.9
  Top Layer w0.203: R462.1@65.802,294.7 72.602,287.9 74.4,287.9 74.67,287.63 74.675,287.63 75.032,287.273 75.032,286.767 74.893,286.629 74.893,286.303 74.938,286.258 74.947,286.267 v2(75.184,286.267) ; v2@69.554,176.854 v2(69.5,176.8) 69.5,225.113 70.605,226.218 70.605,249.675 72.136,251.206 v2(72.136,252.034) ; v2(100.25,100) 128.1,100 149.12,121.02 149.12,121.659 v2(149.149,121.689) ; v2(115.867,274.824) 156.746,233.945 165.593,233.945 166.152,233.386 v2(168.466,233.386) ; v2(200.782,150.3) 203.799,150.3 204.4,150.901 204.4,155.502 204.17,155.732 R329.1@203.811,155.732 204.919,156.84 U45.13@204.919,158.256 ; v2@205.409,239 211.26,239 211.54,238.72 211.54,234.304 R214.1@212.18,233.664 211.072,232.556 U26.13@211.072,231.14
  Signal Layer 2 w0.203: v2(149.149,121.689) 149.149,126.477 172.272,149.6 200.082,149.6 v2(200.782,150.3) ; v2(168.466,233.386) 168.466,233.168 175.525,240.226 201.91,240.226 203.147,238.988 205.174,238.988 v2(205.2,238.962)
  Bottom Layer w0.203: v2(69.5,176.8) 70.4,175.9 70.4,166.2 88.157,148.443 88.157,115.336 99,104.492 98.988,104.48 100.25,103.218 v2(100.25,100) ; v2(72.136,252.034) 72.136,265.776 75.184,268.824 75.184,271.462 ; v2(75.184,286.267) 75.184,286.258 75.616,285.826 75.616,284.555 75.184,284.123 75.184,271.462 ; v2(115.867,274.824) 115.849,274.824 114.519,273.494 112.487,271.462 75.184,271.462
GATES_FLT_L3: R160.1 R229.1 R459.1 U19.13 U27.13 | length 497.6
  Top Layer w0.203: R459.1@65.753,292.1 66.788,292.1 71.788,287.1 71.888,287 71.908,287.02 v2(74.422,287.02) ; v2(68.809,172.484) 68.809,225.415 70.096,226.701 70.096,250.182 v2(71.222,251.308) ; v2(96.5,98) v2(99.25,98) 128.002,98 150.9,120.898 v2(150.9,122.623) ; v2(99.218,91.681) 118.319,91.681 151.694,58.306 201.523,58.306 204.4,61.183 204.4,64.108 R160.1@203.772,64.736 ; v2(203.461,147.779) 210.527,147.779 211.54,146.766 211.54,143.309 R229.1@212.18,142.669 212.18,142.262 211.072,141.154 U27.13@211.072,140.144
  Top Layer w0.229: R160.1@203.772,64.736 204.88,65.844 U19.13@204.88,67.261
  Signal Layer 2 w0.203: v2(150.9,122.623) 150.9,126.966 172.534,148.6 199.882,148.6 200.703,147.779 v2(203.461,147.779)
  Bottom Layer w0.203: v2(68.809,172.484) 65.213,168.887 86.822,147.278 86.822,114.128 94.998,105.952 94.998,105.734 95,99.5 v2(96.5,98) ; v2(71.222,251.308) 71.222,265.989 74.348,269.115 74.348,286.946 v2(74.422,287.02) ; v2(99.218,91.681) 99.218,97.833 99.151,97.901 v2(99.25,98)
GATES_RDY: C475.2 C476.2 C477.2 C478.2 C479.2 C480.2 R159.1 R198.1 R213.1 R228.1 R289.1 R328.1 R359.1 U19.12 U25.12 U26.12 U27.12 U38.12 U45.12 | length 861.7
  Top Layer w0.203: v2(65.532,173.656) 66.383,173.656 67.5,174.773 67.5,225.945 68.89,227.335 68.89,250.754 v2(70.612,252.476) 90.932,272.796 v2(91.44,272.796) ; R359.1@69.359,299.793 69.406,299.793 v2(71.664,297.535) ; v2(96.966,92.4) 118.713,92.4 152.4,58.713 199.658,58.713 201.94,60.995 201.94,64.469 202.207,64.736 R159.1@202.822,64.736 203.222,65.136 203.222,65.642 C480.2@203.34,65.76 203.61,66.03 U19.12@203.61,67.261 ; v2(98.75,99) 127.995,99 v2(150,121.005) ; v2(110.654,272.71) 116.099,272.71 155,233.808 156.142,232.666 164.392,232.666 164.57,232.489 v2(164.57,232.661) ; v2(201.905,242.646) 201.905,246.373 201.898,246.38 202.216,246.698 R289.1@202.82,246.698 ; v2(201.964,152.2) 201.964,155.411 202.285,155.732 R328.1@202.861,155.732 203.261,156.132 203.261,156.637 C475.2@203.379,156.755 203.379,157.068 203.649,157.338 U45.12@203.649,158.256 ; v2(202,148.4) 211.199,148.4 213.93,145.668 213.93,142.99 213.609,142.669 R228.1@213.13,142.669 212.73,142.269 212.73,141.763 C478.2@212.612,141.645 212.612,141.295 212.342,141.025 U27.12@212.342,140.144 ; v2(204.3,239.6) 212.248,239.6 213.929,237.919 213.929,233.988 213.605,233.664 R213.1@213.13,233.664 212.847,233.381 212.847,232.876 C477.2@212.612,232.641 212.612,232.303 212.342,232.033 U26.12@212.342,231.14 ; U25.12@212.34,322.108 212.34,323.339 C476.2@212.61,323.609 213.128,324.127 R198.1@213.128,324.632 213.513,324.632 213.928,325.048 v2(213.928,329.525)
  Top Layer w0.229: R289.1@202.82,246.698 202.82,246.828 203.338,247.346 C479.2@203.338,247.721 203.338,248.032 203.608,248.302 U38.12@203.608,249.222
  Signal Layer 2 w0.203: v2(110.654,272.71) 126.9,288.955 126.9,305.957 141.696,320.753 159.489,320.753 168.969,330.233 209.702,330.233 210.411,329.525 v2(213.928,329.525) ; v2(150,121.005) 150,126.734 172.366,149.1 201.299,149.1 v2(202,148.4) ; v2(164.57,232.661) 164.609,232.7 165.785,232.7 165.795,232.689 166.272,232.689 166.977,233.394 167.613,233.394 175.091,240.872 202.126,240.872 203.398,239.6 v2(204.3,239.6)
  Bottom Layer w0.203: v2(65.532,173.656) 61.828,173.656 61.654,173.482 61.654,168.146 84.322,145.478 84.322,111.938 91.851,104.41 91.853,104.41 92.802,103.46 92.802,97.416 95.527,94.691 96.966,94.691 ; v2(70.612,252.476) 70.612,254.409 70.295,254.726 70.295,266.33 73.603,269.638 73.603,271.964 73.603,295.587 71.664,297.526 v2(71.664,297.535) ; v2(91.44,272.796) 110.568,272.796 v2(110.654,272.71) ; v2(96.966,92.4) 96.966,97.216 v2(98.75,99) ; v2(201.905,242.646) 201.905,241.107 201.9,241.103 203.403,239.6 v2(204.3,239.6) ; v2(201.964,152.2) 201.964,148.435 v2(202,148.4)
GATES_RST: R167.1 R206.1 R221.1 R237.1 R297.1 R336.1 R457.1 | length 834.2
  Top Layer w0.203: v2(65,175.198) 66.114,175.198 66.764,175.847 66.764,226.009 68.3,227.545 68.3,251.239 v2(69.596,252.535) 90.774,273.712 v2(91.44,273.712) ; R457.1@68.468,297.582 v2(71.664,294.386) ; v2(98.25,97) 128,97 151.9,120.9 v2(151.9,121.5) ; v2(98.254,90.932) 117.984,90.932 151.016,57.9 202.188,57.9 205.044,60.756 R167.1@205.044,63.736 ; v2(112.7,273.708) 116.09,273.708 150.988,238.81 156.432,233.367 165.325,233.367 166.002,232.689 167.382,232.689 v2(167.401,232.708) ; v2(205.031,241.3) 205.042,241.311 R297.1@205.042,245.698 ; v2(205.083,147.1) 210.034,147.1 210.908,146.226 R237.1@210.908,143.669 ; v2(205.083,152.205) R336.1@205.083,154.732 ; v2(209.306,329.624) 210.906,328.024 R206.1@210.906,325.632 ; R221.1@210.908,234.664 210.871,234.701 210.908,234.738 v2(210.908,238.1)
  Signal Layer 2 w0.203: v2(112.7,273.708) 127.8,288.808 127.8,305.857 141.847,319.905 159.529,319.905 169.248,329.624 v2(209.306,329.624) ; v2(151.9,121.5) 151.9,127.343 172.657,148.1 199.347,148.1 200.347,147.1 v2(205.083,147.1) ; v2(167.401,232.708) 167.419,232.689 168.635,232.689 175.581,239.635 201.418,239.635 202.953,238.1 v2(210.908,238.1) 210.908,238.614 208.222,241.3 v2(205.031,241.3)
  Bottom Layer w0.203: v2(65,175.198) 61.1,175.198 60.654,174.752 60.654,166.846 82.822,144.678 82.822,111.174 92,101.996 92,93.963 95.031,90.932 v2(98.254,90.932) 98.254,96.996 v2(98.25,97) ; v2(69.596,252.535) 69.596,253.365 69.034,253.927 69.034,266.748 72.761,270.475 72.761,293.289 v2(71.664,294.386) ; v2(91.44,273.712) 112.696,273.712 v2(112.7,273.708) ; v2@205.083,146.89 v2(205.083,152.205)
